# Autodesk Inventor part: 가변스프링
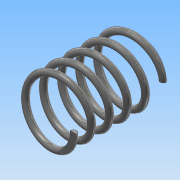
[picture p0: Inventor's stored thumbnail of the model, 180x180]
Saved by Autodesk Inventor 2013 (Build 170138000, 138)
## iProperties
Created: 2017-12
Part Number: 가변스프링
Material: 스테인리스강
Document SubType Name: Modeling
Designer: Administrator
Density: 8.08 g/cm^3
Mass: 7.05423 g
Surface Area: 17.7405 cm^2
Volume: 0.873048 cm^3
Author: Administrator
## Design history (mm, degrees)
sketch "스케치1"
  geometry: L1 (0, 0)-(9, 0); L2 (9, 0)-(9, -22.649); L3 (9, -22.649)-(0, -22.649); L4 (0, -22.649)-(0, 0); C1 r 1 at (9, 0); 1 further point
  constraints: 8 end point, 2 coincident, 2 parallel, 1 centre point, 1 horizontal, 1 perpendicular
  dimensions: "d0" = 18 diameter of L2 L4; "d2" = 22.64928 distance of L1.end L2.end (derived); "d3" = 2 diameter of C1
feature "코일1" sketch "스케치1" pitch "d4" = 10; turns "d6" = 5; dims "d5" = 22.64928 (= d2), "d7" = 0, angle "d8" = 90 deg, angle "d9" = 90 deg, "d10" = 0, "d11" = 0
sketch "스케치2"
  geometry: L1 (0, 15)-(-22.649, 15); L2 (-22.649, 15)-(-22.649, -15); L3 (-22.649, -15)-(0, -15); L4 (0, -15)-(0, 15); 4 further points
  constraints: 8 end point, 2 coincident, 2 midpoint, 2 parallel, 1 horizontal, 1 perpendicular
  dimensions: "d12" = 30 distance of L1.end L2.end
extrude "돌출1" sketch "스케치2" stored distance "d14" = 0; taper "d15" = 0 deg
node "솔리드1"
